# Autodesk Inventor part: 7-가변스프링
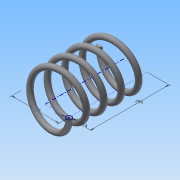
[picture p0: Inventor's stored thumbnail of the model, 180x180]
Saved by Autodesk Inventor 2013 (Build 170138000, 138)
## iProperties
Created: 2015-03
Part Number: 7-가변스프링
Material: 강철, 탄소
Document SubType Name: Modeling
Designer: Administrator
Density: 7.87 g/cm^3
Mass: 48.2733 g
Surface Area: 62.0009 cm^2
Volume: 6.13384 cm^3
Author: Administrator
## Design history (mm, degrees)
sketch "스케치1"
  geometry: L1 (0, 0)-(17.5, 0); L2 (17.5, 0)-(17.5, 43.5); L3 (17.5, 43.5)-(0, 43.5); L4 (0, 43.5)-(0, 0); C1 r 2 at (17.5, 0)
  constraints: 8 end point, 2 parallel, 1 centre point, 1 coincident, 1 horizontal, 1 perpendicular
  dimensions: "d0" = 4 diameter of C1; "d2" = 35 diameter of L2 L4; "d3" = 43.5 distance between parallel lines of L3 L1 (derived)
feature "코일1" sketch "스케치1" pitch "d4" = 10; turns "d6" = 4.5; dims "d5" = 43.5 (= d3), "d7" = 0, angle "d8" = 90 deg, angle "d9" = 90 deg, "d10" = 0, "d11" = 0
sketch "스케치2"
  geometry: L1 (-19.5, 0)-(-15.5, 0) reference; L2 (-19.5, 0)-(-15.5, 0) reference; 1 further point
  constraints: 2 horizontal alignment
extrude "돌출1" cut sketch "스케치2" distance "d12" = 10; taper "d13" = 0 deg
node "작업 평면1"
sketch "스케치3"
  geometry: L1 (-19.5, 0)-(-15.5, 0) reference; 1 further point
  constraints: 1 horizontal alignment
extrude "돌출2" cut sketch "스케치3" distance "d15" = 10; taper "d16" = 0 deg
node "솔리드1"
node "절단 모서리 투영1"
node "절단 모서리 투영2"
node "절단 모서리 투영3"
other parameters: "d14" = -43.5 (= -d3)
